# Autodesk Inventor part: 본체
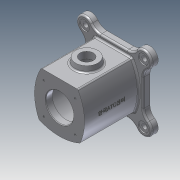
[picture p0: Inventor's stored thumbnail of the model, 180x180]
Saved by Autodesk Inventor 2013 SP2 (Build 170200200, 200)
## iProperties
Created: 2022-01
Part Number: 본체
Material: 알루미늄 6061
Document SubType Name: Modeling
Designer: i
Density: 2.71 g/cm^3
Mass: 1229.2 g
Surface Area: 907.511 cm^2
Volume: 453.578 cm^3
Author: i
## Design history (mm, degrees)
sketch "스케치4"
  geometry: L1 (-53, -53)-(53, -53); L2 (53, -53)-(53, 53); L3 (53, 53)-(-53, 53); L4 (-53, 53)-(-53, -53); L5 (-53, -53)-(53, 53); L6 (53, -53)-(-53, 53); C1 r 15 at (-53, 53); C2 r 15 at (53, 53); C3 r 15 at (-53, -53); C4 r 15 at (53, -53); 1 further point
  constraints: 12 end point, 4 centre point, 4 coincident, 2 midpoint, 2 parallel, 1 horizontal, 1 perpendicular
  dimensions: "d19" = 106 distance of L2.end L3.end; "d20" = 106 distance of L1.end L2.end; "d21" = 30 diameter of C2; "d22" = 30 diameter of C1; "d23" = 30 diameter of C3; "d24" = 30 diameter of C4
extrude "돌출1" new body sketch "스케치4" distance "d25" = 12; taper "d26" = 0 deg
fillet "모깎기1" dims "d27" = 20
sketch "스케치6"
  geometry: L1 (-45, -45)-(45, -45); L2 (45, -45)-(45, 45); L3 (45, 45)-(32.942, 45); L4 (-45, 45)-(-45, 0); L5 (-45, -45)-(45, 45); L6 (45, -45)-(-45, 45); L7 (-32.942, 45)-(-45, 45); L8 (-45, 0)-(-45, -45); L9 (32.942, 45)-(-32.942, 45); A1 r 90 centre (45, 0) between (-32.942, 45) and (-37.029, -37.029); A2 r 90 centre (0, 45) between (-45, -32.942) and (-37.029, -37.029); A3 r 90 centre (-45, 0) between (32.942, -45) and (37.029, -37.029); A4 r 90 centre (0, 45) between (-37.029, -37.029) and (37.029, -37.029); A5 r 90 centre (45, 0) between (-37.029, -37.029) and (-32.942, -45); A6 r 90 centre (-45, 0) between (37.029, -37.029) and (32.942, 45); A7 r 90 centre (0, 45) between (37.029, -37.029) and (45, -32.942); 3 further points
  constraints: 18 end point, 16 point on circle, 9 tangent, 7 centre point, 5 parallel, 5 point on line, 3 midpoint, 1 coincident, 1 horizontal, 1 perpendicular
  dimensions: "d37" = 90 distance of L4.start L2.end; "d38" = 90 distance of L1.end L2.end; "d39" = 90 distance of L7.start A5.end; "d40" = 90 radius of A1; "d41" = 90 distance of A2.start A7.end; "d42" = 90 radius of A2; "d43" = 90 distance of L3.end A3.start; "d44" = 90 radius of A3
extrude "돌출2" join sketch "스케치6" distance "d45" = 98; taper "d46" = 0 deg
sketch "스케치7"
  geometry: L1 (45, 110)-(-37.029, 110) reference; L2 (0, 0)-(0, 110); L3 (0, 110)-(25, 110); L4 (25, 110)-(25, 98); L5 (25, 98)-(34, 98); L6 (37, 95)-(37, 15); L7 (34, 12)-(25, 12); L8 (25, 12)-(25, 0); L9 (25, 0)-(0, 0); A1 r 3 centre (34, 95) between (37, 95) and (34, 98); A2 r 3 centre (34, 15) between (34, 12) and (37, 15)
  constraints: 16 end point, 4 point on circle, 4 tangent, 3 parallel, 3 perpendicular, 2 centre point, 2 point on line, 1 collinear, 1 equal radius
  dimensions: "d48" = 50 diameter of L4 L2; "d51" = 50 diameter of L8 L2; "d52" = 74 diameter of L6 L2; "d53" = 12 distance of L3.end L4.end; "d54" = 12 distance of L7.end L8.end; "d55" = 3 radius of A1
revolve "회전1" sketch "스케치7" stored, may be unused: angle "d56" = 90 deg
node "작업 평면1"
sketch "스케치8"
  geometry: L1 (-24.277, 0)-(24.277, 0) reference; C1 r 20 at (0, 61); 1 further point
  constraints: 1 centre point, 1 vertical alignment
  dimensions: "d58" = 40 diameter of C1; "d59" = 61 distance from line of L1 C1.centre
extrude "돌출3" join sketch "스케치8" stored distance "d60" = 98; taper "d61" = 10 deg
sketch "스케치9"
  geometry: L1 (55, 81)-(55, 41) reference; L2 (55, 61)-(32.622, 61); L3 (55, 61)-(55, 49); L4 (55, 49)-(43, 49); L5 (42, 48)-(42, 46); L6 (42, 46)-(32.622, 46); L7 (42, 48)-(43, 49); L8 (32.622, 61)-(32.622, 46); 2 further points
  constraints: 14 end point, 3 perpendicular, 3 point on line, 1 midpoint
  dimensions: "d62" = 24 diameter of L4 L2; "d64" = 30 diameter of L6 L2; "d65" = 13 distance of L3.end point (42, 49); "d66" = 1 distance of L5.start point (42, 49); "d67" = 1 distance of L4.end point (42, 49) (= d66); "d113" = 22.37792 distance of L2.start L2.end
revolve "회전2" sketch "스케치9" stored, may be unused: angle "d68" = 90 deg
sketch "스케치11"
  geometry: C1 r 75 at (0, 0); A1 r 15 centre (53, -53) between (40.69, -61.571) and (61.571, -40.69) reference; A2 r 15 centre (53, 53) between (61.571, 40.69) and (40.69, 61.571) reference; A3 r 15 centre (-53, 53) between (-40.69, 61.571) and (-61.571, 40.69) reference; A4 r 15 centre (-53, -53) between (-61.571, -40.69) and (-40.69, -61.571) reference; 5 further points
  constraints: 5 coincident, 1 centre point
  dimensions: "d81" = 150 diameter of C1
hole "구멍2" sketch "스케치11" at (-53, 53), (53, 53), (53, -53), (-53, -53) diameter "d82" = 9; stored, may be unused: countersink angle "d86" = 90 deg, drill point angle "d88" = 118 deg; dims "d83" = 9, "d84" = 18, "d85" = 2, "d87" = 11
node "작업 평면2"
sketch "스케치12"
  geometry: L1 (40.69, 0)-(68, 0) reference; L2 (55, 81)-(55, 41) reference; 3 further points
  constraints: 1 other
  dimensions: "d90" = 61 distance from line of L1 point (0, 61); "d91" = 55 distance from line of L2 point (0, 61)
feature "엠보싱1" sketch "스케치12" dims "d37" = 90, "d38" = 90, "d39" = 90, "d40" = 90, "d41" = 90, "d42" = 90, "d43" = 90, "d44" = 90, "d92" = 0.5, "d93" = 0
fillet "모깎기2" dims "d94" = 3
fillet "모깎기3" dims "d95" = 3
chamfer "모따기1" distance "d96" = 1; stored, may be unused: second distance "d97" = 2, angle "d98" = 45 deg
sketch "스케치13" dims "d99" = 80
  geometry: L1 (0, 0)-(28.284, 28.284); L2 (0, 0)-(40, 0); C1 r 26 at (0, 0) reference; 4 further points
  constraints: 4 end point, 2 coincident, 1 equal length, 1 horizontal, 8 other
  dimensions: "d101" = 45 deg angle of L2 L1; "d104" = 360 deg dimension on C1.centre point (28.284, 28.284) (derived)
hole "구멍3" sketch "스케치13" at (28.284, 28.284), (-28.284, 28.284), (-28.284, -28.284), (28.284, -28.284) diameter "d106" = 3.242; stored, may be unused: countersink angle "d110" = 90 deg, drill point angle "d112" = 118 deg; dims "d107" = 9, "d108" = 18, "d109" = 2, "d111" = 11
node "작업 평면4"
node "솔리드1"
mirror "대칭2"
other parameters: "d57" = 55
